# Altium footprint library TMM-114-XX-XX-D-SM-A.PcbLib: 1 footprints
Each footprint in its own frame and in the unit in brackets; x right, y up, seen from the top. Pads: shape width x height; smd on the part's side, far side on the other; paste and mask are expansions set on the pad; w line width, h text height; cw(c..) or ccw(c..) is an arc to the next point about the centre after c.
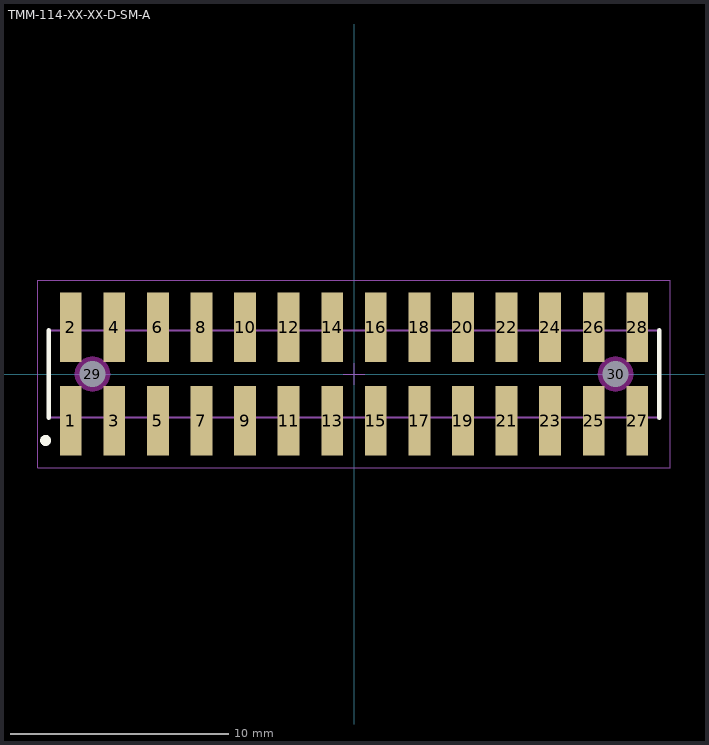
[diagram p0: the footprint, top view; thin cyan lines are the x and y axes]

## TMM-114-XX-XX-D-SM-A [mm] "2.00mm pitch, 28 pin, terminal strip; double row, w/alignment pins, SMT"
height 2.77
pads (30):
  rect 1x3.2 smd mask+0: 1(-13,-2.15) 2(-13,2.15) 3(-11,-2.15) 4(-11,2.15) 5(-9,-2.15) 6(-9,2.15) 7(-7,-2.15) 8(-7,2.15) 9(-5,-2.15) 10(-5,2.15) 11(-3,-2.15) 12(-3,2.15) 13(-1,-2.15) 14(-1,2.15) 15(1,-2.15) 16(1,2.15) 17(3,-2.15) 18(3,2.15) 19(5,-2.15) 20(5,2.15) 21(7,-2.15) 22(7,2.15) 23(9,-2.15) 24(9,2.15) 25(11,-2.15) 26(11,2.15) 27(13,-2.15) 28(13,2.15)
  round 1 hole 1.2 unplated mask+0: 29(-12,0) 30(12,0)
Top Overlay:
  circle w0.25: c-14.15,-3.05 r0.125
  lines w0.2: -14,-2 -14,2 ; 14,-2 14,2
Keep-Out Layer:
  pour cut-out: -11.193,0 -11.221,0.209 -11.301,0.403 -11.429,0.571 -11.597,0.699 -11.791,0.779 -12,0.807 -12.209,0.779 -12.403,0.699 -12.571,0.571 -12.699,0.403 -12.779,0.209 -12.807,0 -12.779,-0.209 -12.699,-0.403 -12.571,-0.571 -12.403,-0.699 -12.209,-0.779 -12,-0.807 -11.791,-0.779 -11.597,-0.699 -11.429,-0.571 -11.301,-0.403 -11.221,-0.209
  pour cut-out: 12.807,0 12.779,0.209 12.699,0.403 12.571,0.571 12.403,0.699 12.209,0.779 12,0.807 11.791,0.779 11.597,0.699 11.429,0.571 11.301,0.403 11.221,0.209 11.193,0 11.221,-0.209 11.301,-0.403 11.429,-0.571 11.597,-0.699 11.791,-0.779 12,-0.807 12.209,-0.779 12.403,-0.699 12.571,-0.571 12.699,-0.403 12.779,-0.209
Mechanical 12:
  lines w0.001: -14,-2 14,-2 14,2 -14,2 -14,-2
Mechanical 13:
  lines w0.1: -14,-2 14,-2 14,2 -14,2 -14,-2
  text ".Designator" at 0,-0.127 h1.52
Mechanical 15:
  lines w0.05: -0.5,0 0.5,0 ; 0,-0.5 0,0.5 ; -14.5,-4.3 14.5,-4.3 14.5,4.3 -14.5,4.3 -14.5,-4.3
